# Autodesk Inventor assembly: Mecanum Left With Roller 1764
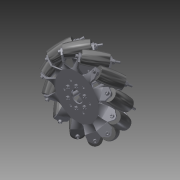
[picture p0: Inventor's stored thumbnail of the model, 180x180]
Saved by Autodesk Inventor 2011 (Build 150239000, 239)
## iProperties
Created: 2011-01
Part Number: Mecanum Left With Roller 1764
Document SubType Name: Assembly
Designer: dfranz
Translation Standard: STEP AP203
FileName: //Amserv/amserver/AndyMark/Products/Wheel Mecanum/8 Mecanum Wheel/8 mecanum left with roller.stp
PreProcessor: Unknown
PostProcessor: Build: 239, Release: 2011 RTM - Date: Wed 02/17/2010
Sent Units: millimeter
Uncertainty: 0.001
Author: dfranz
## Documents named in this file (9)
- R:\2010-2011\CAD\Frame 1764\Drive Train 1764\Wheels 1764\Mecanum Wheel 1764\Mecanum Left 1764\Mecanum Left With Roller 1764.iam
- R:\2010-2011\CAD\Frame 1764\Drive Train 1764\Wheels 1764\Mecanum Wheel 1764\Mecanum Left 1764\#10 LockNut 1764.ipt
- R:\2010-2011\CAD\Frame 1764\Drive Train 1764\Wheels 1764\Mecanum Wheel 1764\Mecanum Left 1764\Middle Axle 1764.ipt
- R:\2010-2011\CAD\Frame 1764\Drive Train 1764\Wheels 1764\Mecanum Wheel 1764\Mecanum Left 1764\MBC Bushing MU04TH04 1764.ipt
- R:\2010-2011\CAD\Frame 1764\Drive Train 1764\Wheels 1764\Mecanum Wheel 1764\Mecanum Left 1764\Washer 1764.ipt
- R:\2010-2011\CAD\Frame 1764\Drive Train 1764\Wheels 1764\Mecanum Wheel 1764\Mecanum Left 1764\SHCS 10-32x3_SHCS 10-32x3 1764.ipt
- R:\2010-2011\CAD\Frame 1764\Drive Train 1764\Wheels 1764\Mecanum Wheel 1764\Mecanum Left 1764\Mid Roller III 1764.ipt
- R:\2010-2011\CAD\Frame 1764\Drive Train 1764\Wheels 1764\Mecanum Wheel 1764\Mecanum Left 1764\8 Mecanum Plate Left 1764.ipt
- R:\2010-2011\CAD\Frame 1764\Drive Train 1764\Wheels 1764\Mecanum Wheel 1764\Mecanum Left 1764\Spacer5 1764.ipt
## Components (116 placed, 8 different names)
1. #10 LockNut 1764:1 — Insert:114
2. #10 LockNut 1764:2 — Insert:65
3. #10 LockNut 1764:3 — Insert:42
4. #10 LockNut 1764:4 — Insert:12
5. #10 LockNut 1764:5 — Insert:11
6. #10 LockNut 1764:6 — Insert:82
7. #10 LockNut 1764:7 — Insert:73
8. #10 LockNut 1764:8 — Insert:26
9. #10 LockNut 1764:9 — Insert:9
10. #10 LockNut 1764:10 — Insert:34
11. #10 LockNut 1764:11 — Insert:8
12. #10 LockNut 1764:12 — Insert:105
13. #10 LockNut 1764:13 — Insert:57
14. #10 LockNut 1764:14 — Insert:10
15. #10 LockNut 1764:15 — Insert:49
16. #10 LockNut 1764:16 — Insert:7
17. #10 LockNut 1764:17 — Insert:97
18. #10 LockNut 1764:18 — Insert:90
19. Middle Axle 1764:1 — Insert:52, Insert:53, Insert:55
20. Middle Axle 1764:2 — Insert:68, Insert:69, Insert:70
21. Middle Axle 1764:3 — Insert:96
22. Middle Axle 1764:4 — Insert:36, Insert:37, Insert:39
23. Middle Axle 1764:5 — Insert:84, Insert:85, Insert:87
24. Middle Axle 1764:6 — Insert:28, Insert:29, Insert:30, Insert:31
25. Middle Axle 1764:7 — Insert:100, Insert:101, Insert:103
26. Middle Axle 1764:8 — Insert:108, Insert:109, Insert:111
27. Middle Axle 1764:9 — Insert:44, Insert:45
28. Middle Axle 1764:10 — Insert:21, Insert:22, Insert:24
29. Middle Axle 1764:11 — Insert:76, Insert:77, Insert:79
30. Middle Axle 1764:12 — Insert:60, Insert:61, Insert:62, Insert:63
31. MBC Bushing MU04TH04 1764:1 — Insert:93
32. MBC Bushing MU04TH04 1764:2 — Insert:95
33. MBC Bushing MU04TH04 1764:3 — Insert:56
34. MBC Bushing MU04TH04 1764:4 — Insert:48
35. MBC Bushing MU04TH04 1764:5 — Insert:104
36. MBC Bushing MU04TH04 1764:6 — Insert:64
37. MBC Bushing MU04TH04 1764:7 — Insert:46, Insert:50
38. MBC Bushing MU04TH04 1764:8 — Insert:86
39. MBC Bushing MU04TH04 1764:9 — Insert:30
40. MBC Bushing MU04TH04 1764:10 — Insert:24
41. MBC Bushing MU04TH04 1764:11 — Insert:32
42. MBC Bushing MU04TH04 1764:12 — Insert:110, Insert:113
43. MBC Bushing MU04TH04 1764:13 — Insert:62
44. MBC Bushing MU04TH04 1764:14 — Insert:112
45. MBC Bushing MU04TH04 1764:15 — Insert:80
46. MBC Bushing MU04TH04 1764:16 — Insert:72
47. MBC Bushing MU04TH04 1764:17 — Insert:88
48. MBC Bushing MU04TH04 1764:18 — Insert:38, Insert:41
49. MBC Bushing MU04TH04 1764:19 — Insert:40
50. MBC Bushing MU04TH04 1764:20 — Insert:23
51. MBC Bushing MU04TH04 1764:21 — Insert:78, Insert:81
52. MBC Bushing MU04TH04 1764:22 — Insert:54, Insert:58
53. MBC Bushing MU04TH04 1764:23 — Insert:71, Insert:74
54. MBC Bushing MU04TH04 1764:24 — Insert:102
55. Washer 1764:1 — Insert:53, Insert:54
56. Washer 1764:2 — Insert:92, Insert:93, Insert:98
57. Washer 1764:3 — Insert:70, Insert:72
58. Washer 1764:4 — Insert:85, Insert:86
59. Washer 1764:5 — Insert:22, Insert:23
60. Washer 1764:6 — Insert:109, Insert:110
61. Washer 1764:7 — Insert:94, Insert:95, Insert:96
62. Washer 1764:8 — Insert:31, Insert:32
63. Washer 1764:9 — Insert:61, Insert:66
64. Washer 1764:10 — Insert:103, Insert:104
65. Washer 1764:11 — Insert:63, Insert:64
66. Washer 1764:12 — Insert:37, Insert:38
67. Washer 1764:13 — Insert:79, Insert:80
68. Washer 1764:14 — Insert:39, Insert:40
69. Washer 1764:15 — Insert:20, Insert:21, Insert:25
70. Washer 1764:16 — Insert:77, Insert:78
71. Washer 1764:17 — Insert:29, Insert:33
72. Washer 1764:18 — Insert:55, Insert:56
73. Washer 1764:19 — Insert:111, Insert:112
74. Washer 1764:20 — Insert:101, Insert:102, Insert:106
75. Washer 1764:21 — Insert:45, Insert:46
76. Washer 1764:22 — Insert:87, Insert:88, Insert:89
77. Washer 1764:23 — Insert:69, Insert:71
78. Washer 1764:24 — Insert:47, Insert:48
79. SHCS 10-32x3_SHCS 10-32x3 1764:1 — Insert:3
80. SHCS 10-32x3_SHCS 10-32x3 1764:2 — Insert:99
81. SHCS 10-32x3_SHCS 10-32x3 1764:3 — Insert:43
82. SHCS 10-32x3_SHCS 10-32x3 1764:4 — Insert:19
83. SHCS 10-32x3_SHCS 10-32x3 1764:5 — Insert:5
84. SHCS 10-32x3_SHCS 10-32x3 1764:6 — Insert:4
85. SHCS 10-32x3_SHCS 10-32x3 1764:7 — Insert:59
86. SHCS 10-32x3_SHCS 10-32x3 1764:8 — Insert:35
87. SHCS 10-32x3_SHCS 10-32x3 1764:9 — Insert:107
88. SHCS 10-32x3_SHCS 10-32x3 1764:10 — Insert:91
89. SHCS 10-32x3_SHCS 10-32x3 1764:11 — Insert:2
90. SHCS 10-32x3_SHCS 10-32x3 1764:12 — Insert:67
91. SHCS 10-32x3_SHCS 10-32x3 1764:13 — Insert:83
92. SHCS 10-32x3_SHCS 10-32x3 1764:14 — Insert:1
93. SHCS 10-32x3_SHCS 10-32x3 1764:15 — Insert:75
94. SHCS 10-32x3_SHCS 10-32x3 1764:16 — Insert:27
95. SHCS 10-32x3_SHCS 10-32x3 1764:17 — Insert:51
96. SHCS 10-32x3_SHCS 10-32x3 1764:18 — Insert:6
97. Mid Roller III 1764:1 — Insert:74
98. Mid Roller III 1764:2 — Insert:106
99. Mid Roller III 1764:3 — Insert:25
100. Mid Roller III 1764:4 — Insert:33
101. Mid Roller III 1764:5 — Insert:66
102. Mid Roller III 1764:6 — Insert:113
103. Mid Roller III 1764:7 — Insert:50
104. Mid Roller III 1764:8 — Insert:58
105. Mid Roller III 1764:9 — Insert:81
106. Mid Roller III 1764:10 — Insert:98
107. Mid Roller III 1764:11 — Insert:41
108. Mid Roller III 1764:12 — Insert:89
109. 8 Mecanum Plate Left 1764:1 — Mate:1, Mate:2, Mate:3, Insert:1, Insert:2, Insert:3, Insert:4, Insert:5, Insert:6, Insert:13, Insert:14, Insert:15, Insert:16, Insert:17, Insert:18, Insert:19, Insert:20, Insert:27, Insert:28, Insert:35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
110. 8 Mecanum Plate Left 1764:2 — Mate:1, Mate:2, Mate:3, Insert:7, Insert:8, Insert:9, Insert:10, Insert:11, Insert:12, Insert:26, Insert:34, Insert:42, Insert:47, Insert:49, Insert:57, Insert:65, Insert:73, Insert:82, Insert:90, Insert:94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
111. Spacer5 1764:1 — Insert:15
112. Spacer5 1764:2 — Insert:13
113. Spacer5 1764:3 — Insert:18
114. Spacer5 1764:4 — Insert:14
115. Spacer5 1764:5 — Insert:16
116. Spacer5 1764:6 — Insert:17
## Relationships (117: Insert 114, Mate 3)
- Mate:1: 8 Mecanum Plate Left 1764:1 ↔ 8 Mecanum Plate Left 1764:2
- Mate:2: 8 Mecanum Plate Left 1764:1 ↔ 8 Mecanum Plate Left 1764:2
- Mate:3: 8 Mecanum Plate Left 1764:1 ↔ 8 Mecanum Plate Left 1764:2
- Insert:1: SHCS 10-32x3_SHCS 10-32x3 1764:14 ↔ 8 Mecanum Plate Left 1764:1
- Insert:2: SHCS 10-32x3_SHCS 10-32x3 1764:11 ↔ 8 Mecanum Plate Left 1764:1
- Insert:3: SHCS 10-32x3_SHCS 10-32x3 1764:1 ↔ 8 Mecanum Plate Left 1764:1
- Insert:4: SHCS 10-32x3_SHCS 10-32x3 1764:6 ↔ 8 Mecanum Plate Left 1764:1
- Insert:5: SHCS 10-32x3_SHCS 10-32x3 1764:5 ↔ 8 Mecanum Plate Left 1764:1
- Insert:6: SHCS 10-32x3_SHCS 10-32x3 1764:18 ↔ 8 Mecanum Plate Left 1764:1
- Insert:7: #10 LockNut 1764:16 ↔ 8 Mecanum Plate Left 1764:2
- Insert:8: #10 LockNut 1764:11 ↔ 8 Mecanum Plate Left 1764:2
- Insert:9: #10 LockNut 1764:9 ↔ 8 Mecanum Plate Left 1764:2
- Insert:10: #10 LockNut 1764:14 ↔ 8 Mecanum Plate Left 1764:2
- Insert:11: #10 LockNut 1764:5 ↔ 8 Mecanum Plate Left 1764:2
- Insert:12: #10 LockNut 1764:4 ↔ 8 Mecanum Plate Left 1764:2
- Insert:13: 8 Mecanum Plate Left 1764:1 ↔ Spacer5 1764:2
- Insert:14: 8 Mecanum Plate Left 1764:1 ↔ Spacer5 1764:4
- Insert:15: 8 Mecanum Plate Left 1764:1 ↔ Spacer5 1764:1
- Insert:16: 8 Mecanum Plate Left 1764:1 ↔ Spacer5 1764:5
- Insert:17: 8 Mecanum Plate Left 1764:1 ↔ Spacer5 1764:6
- Insert:18: 8 Mecanum Plate Left 1764:1 ↔ Spacer5 1764:3
- Insert:19: SHCS 10-32x3_SHCS 10-32x3 1764:4 ↔ 8 Mecanum Plate Left 1764:1
- Insert:20: Washer 1764:15 ↔ 8 Mecanum Plate Left 1764:1
- Insert:21: Middle Axle 1764:10 ↔ Washer 1764:15
- Insert:22: Middle Axle 1764:10 ↔ Washer 1764:5
- Insert:23: MBC Bushing MU04TH04 1764:20 ↔ Washer 1764:5
- Insert:24: Middle Axle 1764:10 ↔ MBC Bushing MU04TH04 1764:10
- Insert:25: Washer 1764:15 ↔ Mid Roller III 1764:3
- Insert:26: #10 LockNut 1764:8 ↔ 8 Mecanum Plate Left 1764:2
- Insert:27: SHCS 10-32x3_SHCS 10-32x3 1764:16 ↔ 8 Mecanum Plate Left 1764:1
- Insert:28: Middle Axle 1764:6 ↔ 8 Mecanum Plate Left 1764:1
- Insert:29: Middle Axle 1764:6 ↔ Washer 1764:17
- Insert:30: Middle Axle 1764:6 ↔ MBC Bushing MU04TH04 1764:9
- Insert:31: Middle Axle 1764:6 ↔ Washer 1764:8
- Insert:32: MBC Bushing MU04TH04 1764:11 ↔ Washer 1764:8
- Insert:33: Washer 1764:17 ↔ Mid Roller III 1764:4
- Insert:34: #10 LockNut 1764:10 ↔ 8 Mecanum Plate Left 1764:2
- Insert:35: SHCS 10-32x3_SHCS 10-32x3 1764:8 ↔ 8 Mecanum Plate Left 1764:1
- Insert:36: Middle Axle 1764:4 ↔ 8 Mecanum Plate Left 1764:1
- Insert:37: Middle Axle 1764:4 ↔ Washer 1764:12
- Insert:38: MBC Bushing MU04TH04 1764:18 ↔ Washer 1764:12
- Insert:39: Middle Axle 1764:4 ↔ Washer 1764:14
- Insert:40: MBC Bushing MU04TH04 1764:19 ↔ Washer 1764:14
- Insert:41: MBC Bushing MU04TH04 1764:18 ↔ Mid Roller III 1764:11
- Insert:42: #10 LockNut 1764:3 ↔ 8 Mecanum Plate Left 1764:2
- Insert:43: SHCS 10-32x3_SHCS 10-32x3 1764:3 ↔ 8 Mecanum Plate Left 1764:1
- Insert:44: Middle Axle 1764:9 ↔ 8 Mecanum Plate Left 1764:1
- Insert:45: Middle Axle 1764:9 ↔ Washer 1764:21
- Insert:46: MBC Bushing MU04TH04 1764:7 ↔ Washer 1764:21
- Insert:47: Washer 1764:24 ↔ 8 Mecanum Plate Left 1764:2
- Insert:48: MBC Bushing MU04TH04 1764:4 ↔ Washer 1764:24
- Insert:49: #10 LockNut 1764:15 ↔ 8 Mecanum Plate Left 1764:2
- Insert:50: MBC Bushing MU04TH04 1764:7 ↔ Mid Roller III 1764:7
- Insert:51: SHCS 10-32x3_SHCS 10-32x3 1764:17 ↔ 8 Mecanum Plate Left 1764:1
- Insert:52: Middle Axle 1764:1 ↔ 8 Mecanum Plate Left 1764:1
- Insert:53: Middle Axle 1764:1 ↔ Washer 1764:1
- Insert:54: MBC Bushing MU04TH04 1764:22 ↔ Washer 1764:1
- Insert:55: Middle Axle 1764:1 ↔ Washer 1764:18
- Insert:56: MBC Bushing MU04TH04 1764:3 ↔ Washer 1764:18
- Insert:57: #10 LockNut 1764:13 ↔ 8 Mecanum Plate Left 1764:2
- Insert:58: MBC Bushing MU04TH04 1764:22 ↔ Mid Roller III 1764:8
- Insert:59: SHCS 10-32x3_SHCS 10-32x3 1764:7 ↔ 8 Mecanum Plate Left 1764:1
- Insert:60: Middle Axle 1764:12 ↔ 8 Mecanum Plate Left 1764:1
- Insert:61: Middle Axle 1764:12 ↔ Washer 1764:9
- Insert:62: Middle Axle 1764:12 ↔ MBC Bushing MU04TH04 1764:13
- Insert:63: Middle Axle 1764:12 ↔ Washer 1764:11
- Insert:64: MBC Bushing MU04TH04 1764:6 ↔ Washer 1764:11
- Insert:65: #10 LockNut 1764:2 ↔ 8 Mecanum Plate Left 1764:2
- Insert:66: Washer 1764:9 ↔ Mid Roller III 1764:5
- Insert:67: SHCS 10-32x3_SHCS 10-32x3 1764:12 ↔ 8 Mecanum Plate Left 1764:1
- Insert:68: Middle Axle 1764:2 ↔ 8 Mecanum Plate Left 1764:1
- Insert:69: Middle Axle 1764:2 ↔ Washer 1764:23
- Insert:70: Middle Axle 1764:2 ↔ Washer 1764:3
- Insert:71: MBC Bushing MU04TH04 1764:23 ↔ Washer 1764:23
- Insert:72: MBC Bushing MU04TH04 1764:16 ↔ Washer 1764:3
- Insert:73: #10 LockNut 1764:7 ↔ 8 Mecanum Plate Left 1764:2
- Insert:74: MBC Bushing MU04TH04 1764:23 ↔ Mid Roller III 1764:1
- Insert:75: SHCS 10-32x3_SHCS 10-32x3 1764:15 ↔ 8 Mecanum Plate Left 1764:1
- Insert:76: Middle Axle 1764:11 ↔ 8 Mecanum Plate Left 1764:1
- Insert:77: Middle Axle 1764:11 ↔ Washer 1764:16
- Insert:78: MBC Bushing MU04TH04 1764:21 ↔ Washer 1764:16
- Insert:79: Middle Axle 1764:11 ↔ Washer 1764:13
- Insert:80: MBC Bushing MU04TH04 1764:15 ↔ Washer 1764:13
- Insert:81: MBC Bushing MU04TH04 1764:21 ↔ Mid Roller III 1764:9
- Insert:82: #10 LockNut 1764:6 ↔ 8 Mecanum Plate Left 1764:2
- Insert:83: SHCS 10-32x3_SHCS 10-32x3 1764:13 ↔ 8 Mecanum Plate Left 1764:1
- Insert:84: Middle Axle 1764:5 ↔ 8 Mecanum Plate Left 1764:1
- Insert:85: Middle Axle 1764:5 ↔ Washer 1764:4
- Insert:86: MBC Bushing MU04TH04 1764:8 ↔ Washer 1764:4
- Insert:87: Middle Axle 1764:5 ↔ Washer 1764:22
- Insert:88: MBC Bushing MU04TH04 1764:17 ↔ Washer 1764:22
- Insert:89: Washer 1764:22 ↔ Mid Roller III 1764:12
- Insert:90: #10 LockNut 1764:18 ↔ 8 Mecanum Plate Left 1764:2
- Insert:91: SHCS 10-32x3_SHCS 10-32x3 1764:10 ↔ 8 Mecanum Plate Left 1764:1
- Insert:92: Washer 1764:2 ↔ 8 Mecanum Plate Left 1764:1
- Insert:93: MBC Bushing MU04TH04 1764:1 ↔ Washer 1764:2
- Insert:94: Washer 1764:7 ↔ 8 Mecanum Plate Left 1764:2
- Insert:95: MBC Bushing MU04TH04 1764:2 ↔ Washer 1764:7
- Insert:96: Middle Axle 1764:3 ↔ Washer 1764:7
- Insert:97: #10 LockNut 1764:17 ↔ 8 Mecanum Plate Left 1764:2
- Insert:98: Washer 1764:2 ↔ Mid Roller III 1764:10
- Insert:99: SHCS 10-32x3_SHCS 10-32x3 1764:2 ↔ 8 Mecanum Plate Left 1764:1
- Insert:100: Middle Axle 1764:7 ↔ 8 Mecanum Plate Left 1764:1
- Insert:101: Middle Axle 1764:7 ↔ Washer 1764:20
- Insert:102: MBC Bushing MU04TH04 1764:24 ↔ Washer 1764:20
- Insert:103: Middle Axle 1764:7 ↔ Washer 1764:10
- Insert:104: MBC Bushing MU04TH04 1764:5 ↔ Washer 1764:10
- Insert:105: #10 LockNut 1764:12 ↔ 8 Mecanum Plate Left 1764:2
- Insert:106: Washer 1764:20 ↔ Mid Roller III 1764:2
- Insert:107: SHCS 10-32x3_SHCS 10-32x3 1764:9 ↔ 8 Mecanum Plate Left 1764:1
- Insert:108: Middle Axle 1764:8 ↔ 8 Mecanum Plate Left 1764:1
- Insert:109: Middle Axle 1764:8 ↔ Washer 1764:6
- Insert:110: MBC Bushing MU04TH04 1764:12 ↔ Washer 1764:6
- Insert:111: Middle Axle 1764:8 ↔ Washer 1764:19
- Insert:112: MBC Bushing MU04TH04 1764:14 ↔ Washer 1764:19
- Insert:113: MBC Bushing MU04TH04 1764:12 ↔ Mid Roller III 1764:6
- Insert:114: #10 LockNut 1764:1 ↔ 8 Mecanum Plate Left 1764:2
